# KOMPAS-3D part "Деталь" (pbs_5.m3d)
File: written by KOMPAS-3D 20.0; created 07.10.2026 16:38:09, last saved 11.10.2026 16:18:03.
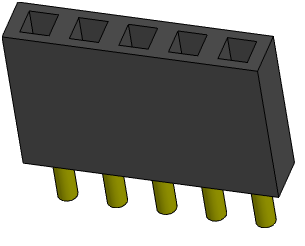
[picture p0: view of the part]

Document properties: Полное имя файла: D:\myProjects\Progect_esp32\box_compas\pbs_5.m3d

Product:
- Part/product: Деталь
    Масса: 0.00157243

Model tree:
1. Эскиз:1
2. Элемент выдавливания:1
     Расстояние 1 = 8.5
3. Эскиз:2  (with: Элемент выдавливания:1)
4. Элемент выдавливания:2
     Расстояние 1 = 3
5. Массив по сетке:2  (with: Элемент выдавливания:2, Эскиз:2)  (5 pattern instances)
     Шаг 1 = 2.54; Угол раствора = 90
6. Эскиз:3  (with: Элемент выдавливания:1)
7. Элемент выдавливания:3
     Расстояние 2 = 8
8. Массив по сетке:3  (with: Элемент выдавливания:3, Эскиз:3)  (5 pattern instances)
     Шаг 1 = 2.54; Угол раствора = 90; Геометрический массив = 128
